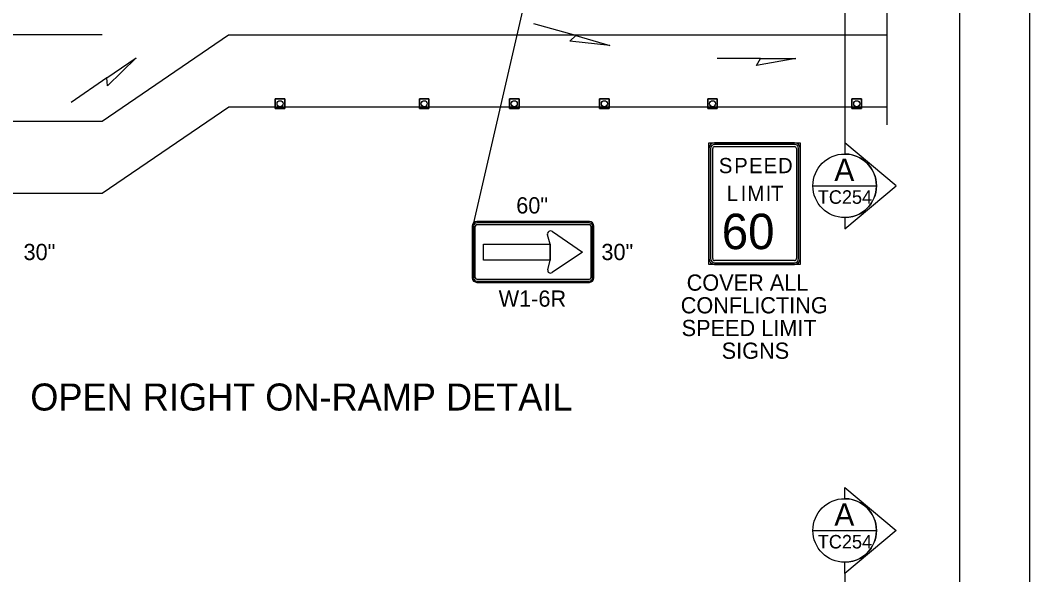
# Model space of a CAD drawing. Extents: x 99999 to 100116, y 99995 to 100013.
# Drawn here: x 100051.58 to 100056.062, y 100004.712 to 100007.175 of the extents above; entities that cross this region are included whole.
import ezdxf

# ---------------------------------------------------------------- set-up
doc = ezdxf.new("R2010")
doc.units = 0
for name, color, linetype in [('RD_MK_LineEdgeYellow', 7, 'Continuous'), ('RD_MK_LineLane', 7, 'Continuous'), ('SH_DE_DetailHeading2Text', 7, 'Continuous'), ('SH_GI_PlotLimits', 7, 'Continuous'), ('SH_GI_SheetBorder', 7, 'Continuous'), ('SH_TI_WZSectionCut', 7, 'Continuous'), ('TR_SN_ConstructionSigns', 7, 'Continuous'), ('TR_WZ_TrafficCone', 7, 'Continuous'), ('TR_WZ_WorkZoneDetails', 7, 'Continuous')]:
    doc.layers.add(name, color=color, linetype=linetype)

msp = doc.modelspace()

# ---------------------------------------------------------------- linework, layer by layer
at = {"layer": 'RD_MK_LineEdgeYellow'}
for p, q in [((100051.9445, 100006.7269), (100052.5055, 100007.1109)), ((100052.5055, 100007.1109), (100055.43, 100007.1109)), ((100051.2543, 100006.7269), (100051.9445, 100006.7269))]:
    msp.add_line(p, q, dxfattribs=at)
at = {"layer": 'RD_MK_LineLane'}
msp.add_lwpolyline([(100051.9445, 100007.1109), (100051.1912, 100007.1109)], dxfattribs=at)
at = {"layer": 'SH_GI_PlotLimits'}
msp.add_lwpolyline([(100039.0625, 99999.6875), (100056.0625, 99999.6875), (100056.0625, 100010.6875), (100039.0625, 100010.6875)], close=True, dxfattribs=at)
at = {"layer": 'SH_GI_SheetBorder'}
msp.add_line((100055.75, 100010.375), (100055.75, 100000), dxfattribs=at)
at = {"layer": 'SH_TI_WZSectionCut'}
for p, q in [((100055.2407, 100008.3589), (100055.2407, 100006.6309)), ((100055.2407, 100006.6309), (100055.2407, 100006.581)), ((100055.4689, 100006.4398), (100055.2407, 100006.6309)), ((100055.2407, 100006.2486), (100055.4689, 100006.4398)), ((100055.2407, 100006.2985), (100055.2407, 100006.2486)), ((100055.2407, 100005.0503), (100055.2407, 100005.1002)), ((100055.2407, 100005.1002), (100055.4688, 100004.9091)), ((100055.4688, 100004.9091), (100055.2407, 100004.718)), ((100055.2407, 100004.718), (100055.2407, 100004.7679)), ((100055.2407, 100004.718), (100055.2407, 100002.99))]:
    msp.add_line(p, q, dxfattribs=at)
for points in [[(100055.0995, 100006.4398), (100055.3819, 100006.4398)], [(100055.0995, 100004.9091), (100055.3819, 100004.9091)]]:
    msp.add_lwpolyline(points, dxfattribs=at)
for centre in [(100055.2407, 100006.4398), (100055.2407, 100004.9091)]:
    msp.add_circle(centre, 0.1412, dxfattribs=at)
for centre in [(100055.2407, 100006.4398), (100055.2407, 100004.9091)]:
    msp.add_arc(centre, 0.1412, 269.9978, 90.0022, dxfattribs=at)
at = {"layer": 'TR_SN_ConstructionSigns'}
for p, q in [((100054.6633, 100006.6309), (100055.0177, 100006.6309)), ((100055.0177, 100006.6309), (100054.6633, 100006.6309)), ((100054.638, 100006.1162), (100054.638, 100006.6056)), ((100054.638, 100006.6056), (100054.638, 100006.1162)), ((100054.6451, 100006.6056), (100054.6451, 100006.1162)), ((100054.6549, 100006.1162), (100054.6549, 100006.6056)), ((100055.0177, 100006.6239), (100054.6633, 100006.6239)), ((100054.6633, 100006.614), (100055.0177, 100006.614)), ((100055.0261, 100006.6056), (100055.0261, 100006.1162)), ((100055.036, 100006.1162), (100055.036, 100006.6056)), ((100055.043, 100006.6056), (100055.043, 100006.1162)), ((100055.043, 100006.1162), (100055.043, 100006.6056)), ((100054.1072, 100006.2809), (100053.6077, 100006.2809)), ((100054.1072, 100006.2753), (100053.6077, 100006.2753)), ((100053.6077, 100006.2674), (100054.1072, 100006.2674)), ((100053.5874, 100006.2607), (100053.5874, 100006.0312)), ((100053.593, 100006.2607), (100053.593, 100006.0312)), ((100053.6009, 100006.0312), (100053.6009, 100006.2607)), ((100053.9326, 100006.1812), (100053.9211, 100006.2218)), ((100053.9436, 100006.2371), (100054.0768, 100006.1452)), ((100054.1139, 100006.2607), (100054.1139, 100006.0312)), ((100054.1218, 100006.0312), (100054.1218, 100006.2607)), ((100054.1274, 100006.0312), (100054.1274, 100006.2607)), ((100053.638, 100006.1092), (100053.638, 100006.1812)), ((100053.638, 100006.1812), (100053.9326, 100006.1812)), ((100053.9326, 100006.1794), (100053.9326, 100006.1812)), ((100053.9326, 100006.1812), (100053.9326, 100006.1794)), ((100053.9326, 100006.111), (100053.9326, 100006.1794)), ((100053.9326, 100006.1794), (100053.9326, 100006.111)), ((100054.0768, 100006.1452), (100053.9417, 100006.055)), ((100053.9326, 100006.1092), (100053.638, 100006.1092)), ((100053.9232, 100006.0673), (100053.9326, 100006.1092)), ((100053.9326, 100006.1092), (100053.9326, 100006.111)), ((100053.9326, 100006.111), (100053.9326, 100006.1092)), ((100055.0177, 100006.1078), (100054.6633, 100006.1078)), ((100054.6633, 100006.0979), (100055.0177, 100006.0979)), ((100055.0177, 100006.0909), (100054.6633, 100006.0909)), ((100054.6633, 100006.0909), (100055.0177, 100006.0909)), ((100054.1072, 100006.0244), (100053.6077, 100006.0244)), ((100053.6077, 100006.0165), (100054.1072, 100006.0165)), ((100053.6077, 100006.0109), (100054.1072, 100006.0109))]:
    msp.add_line(p, q, dxfattribs=at)
msp.add_lwpolyline([(100054.638, 100006.6309), (100055.043, 100006.6309), (100055.043, 100006.0909), (100054.638, 100006.0909)], close=True, dxfattribs=at)
for centre, radius, start, end in [((100054.6633, 100006.6056), 0.0253, 90, 180), ((100054.6633, 100006.6056), 0.0253, 90, 180), ((100055.0177, 100006.6056), 0.0253, 0, 90), ((100055.0177, 100006.6056), 0.0253, 360, 90), ((100054.6633, 100006.6056), 0.0183, 90, 180), ((100054.6633, 100006.6056), 0.00844, 90, 180), ((100055.0177, 100006.6056), 0.0183, 0, 90), ((100055.0177, 100006.6056), 0.00844, 360, 90), ((100053.6077, 100006.2607), 0.0202, 90, 180), ((100053.6077, 100006.2607), 0.0146, 90, 180), ((100053.6077, 100006.2607), 0.00675, 90, 180), ((100054.1072, 100006.2607), 0.0202, 360, 90), ((100054.1072, 100006.2607), 0.0146, 360, 90), ((100054.1072, 100006.2607), 0.00675, 360, 90), ((100054.6633, 100006.1162), 0.0253, 180, 270), ((100054.6633, 100006.1162), 0.0253, 180, 270), ((100054.6633, 100006.1162), 0.0183, 180, 270), ((100054.6633, 100006.1162), 0.00844, 180, 270), ((100055.0177, 100006.1162), 0.0253, 270, 0), ((100055.0177, 100006.1162), 0.0183, 270, 360), ((100055.0177, 100006.1162), 0.00844, 270, 0), ((100055.0177, 100006.1162), 0.0253, 270, 0), ((100053.6077, 100006.0312), 0.0202, 180, 270), ((100053.6077, 100006.0312), 0.0146, 180, 270), ((100053.6077, 100006.0312), 0.00675, 180, 270), ((100054.1072, 100006.0312), 0.0202, 270, 0), ((100054.1072, 100006.0312), 0.0146, 270, 0), ((100054.1072, 100006.0312), 0.00675, 270, 0)]:
    msp.add_arc(centre, radius, start, end, dxfattribs=at)
for centre, major_axis, ratio, start_param, end_param in [((100053.9352, 100006.2256), (-0.0142, -0.0039), 0.918316, 3.856871, 6.283185), ((100053.9352, 100006.0647), (0.0109, 0.0073), 0.895682, 2.286075, 4.712389)]:
    msp.add_ellipse(centre, major_axis=major_axis, ratio=ratio, start_param=start_param, end_param=end_param, dxfattribs=at)
at = {"layer": 'TR_WZ_TrafficCone'}
for points in [[(100052.7126, 100006.8256), (100052.7553, 100006.8256), (100052.7553, 100006.7829), (100052.7126, 100006.7829), (100052.7126, 100006.8256)], [(100052.7126, 100006.7829), (100052.7553, 100006.7829), (100052.7553, 100006.8256), (100052.7126, 100006.8256), (100052.7126, 100006.7829)], [(100053.3526, 100006.8256), (100053.3953, 100006.8256), (100053.3953, 100006.7829), (100053.3526, 100006.7829), (100053.3526, 100006.8256)], [(100053.3526, 100006.7829), (100053.3953, 100006.7829), (100053.3953, 100006.8256), (100053.3526, 100006.8256), (100053.3526, 100006.7829)], [(100053.7526, 100006.8256), (100053.7953, 100006.8256), (100053.7953, 100006.7829), (100053.7526, 100006.7829), (100053.7526, 100006.8256)], [(100053.7526, 100006.7829), (100053.7953, 100006.7829), (100053.7953, 100006.8256), (100053.7526, 100006.8256), (100053.7526, 100006.7829)], [(100054.1526, 100006.8256), (100054.1953, 100006.8256), (100054.1953, 100006.7829), (100054.1526, 100006.7829), (100054.1526, 100006.8256)], [(100054.1526, 100006.7829), (100054.1953, 100006.7829), (100054.1953, 100006.8256), (100054.1526, 100006.8256), (100054.1526, 100006.7829)], [(100054.6326, 100006.8256), (100054.6753, 100006.8256), (100054.6753, 100006.7829), (100054.6326, 100006.7829), (100054.6326, 100006.8256)], [(100054.6326, 100006.7829), (100054.6753, 100006.7829), (100054.6753, 100006.8256), (100054.6326, 100006.8256), (100054.6326, 100006.7829)], [(100055.2726, 100006.8256), (100055.3153, 100006.8256), (100055.3153, 100006.7829), (100055.2726, 100006.7829), (100055.2726, 100006.8256)], [(100055.2726, 100006.7829), (100055.3153, 100006.7829), (100055.3153, 100006.8256), (100055.2726, 100006.8256), (100055.2726, 100006.7829)]]:
    msp.add_lwpolyline(points, dxfattribs=at)
for centre in [(100052.7339, 100006.8042), (100053.3739, 100006.8042), (100053.7739, 100006.8042), (100054.1739, 100006.8042), (100054.6539, 100006.8042), (100055.2939, 100006.8042)]:
    msp.add_circle(centre, 0.0133, dxfattribs=at)
at = {"layer": 'TR_WZ_WorkZoneDetails'}
for p, q in [((100053.8574, 100007.4207), (100053.5933, 100006.275)), ((100054.0465, 100007.1067), (100053.8611, 100007.1597)), ((100054.8672, 100007.0048), (100054.6743, 100007.0048)), ((100051.9656, 100006.9189), (100051.8064, 100006.81)), ((100051.9445, 100006.4069), (100052.5067, 100006.7909)), ((100052.5067, 100006.7909), (100055.43, 100006.7909)), ((100051.292, 100006.4069), (100051.9445, 100006.4069))]:
    msp.add_line(p, q, dxfattribs=at)
msp.add_lwpolyline([(100055.43, 100006.7109), (100055.43, 100007.433), (100055.366, 100007.433), (100055.494, 100007.5569), (100055.43, 100007.5569), (100055.43, 100008.2789)], dxfattribs=at)
for points in [[(100054.1977, 100007.0635), (100054.0209, 100007.0819), (100054.0465, 100007.1067)], [(100052.0953, 100007.0077), (100051.9683, 100006.8834), (100051.9656, 100006.9189)], [(100055.0245, 100007.0048), (100054.8494, 100006.974), (100054.8672, 100007.0048)]]:
    msp.add_lwpolyline(points, close=True, dxfattribs=at)

# ---------------------------------------------------------------- texts
at = {"layer": 'SH_DE_DetailHeading2Text'}
msp.add_text('OPEN RIGHT ON-RAMP DETAIL', height=0.12, rotation=360, dxfattribs=at).set_placement((100051.6253, 100005.4418))
at = {"layer": 'SH_TI_WZSectionCut'}
for s, height, rotation, p in [('A', 0.1, 0.01, (100055.1945, 100006.4604)), ('TC254', 0.06, 360, (100055.1214, 100006.3598)), ('A', 0.1, 0.01, (100055.1945, 100004.9297)), ('TC254', 0.06, 360, (100055.1214, 100004.8291))]:
    msp.add_text(s, height=height, rotation=rotation, dxfattribs=at).set_placement(p)
at = {"layer": 'TR_SN_ConstructionSigns'}
for s, height, p in [('S', 0.0675, (100054.6819, 100006.4959)), ('P', 0.0675, (100054.7501, 100006.4959)), ('E', 0.0675, (100054.8162, 100006.4959)), ('E', 0.0675, (100054.8803, 100006.4959)), ('D', 0.0675, (100054.9445, 100006.4959)), ('L', 0.0675, (100054.717, 100006.3722)), ('I', 0.0675, (100054.7791, 100006.3722)), ('M', 0.0675, (100054.8088, 100006.3722)), ('I', 0.0675, (100054.8898, 100006.3722)), ('T', 0.0675, (100054.9134, 100006.3722)), ('60', 0.1575, (100054.6949, 100006.1584)), ('COVER ALL', 0.072, (100054.5392, 100005.9739)), ('CONFLICTING', 0.072, (100054.5128, 100005.8731)), ('SPEED LIMIT', 0.072, (100054.5168, 100005.7723)), ('SIGNS', 0.072, (100054.6947, 100005.6715))]:
    msp.add_text(s, height=height, dxfattribs=at).set_placement(p)
for s, p in [('60"', (100053.7826, 100006.3169)), ('30"', (100051.5953, 100006.1099)), ('30"', (100054.1607, 100006.1099)), ('W1-6R', (100053.7046, 100005.9029))]:
    msp.add_text(s, height=0.072, rotation=360, dxfattribs=at).set_placement(p)

doc.saveas('drawing.dxf')
